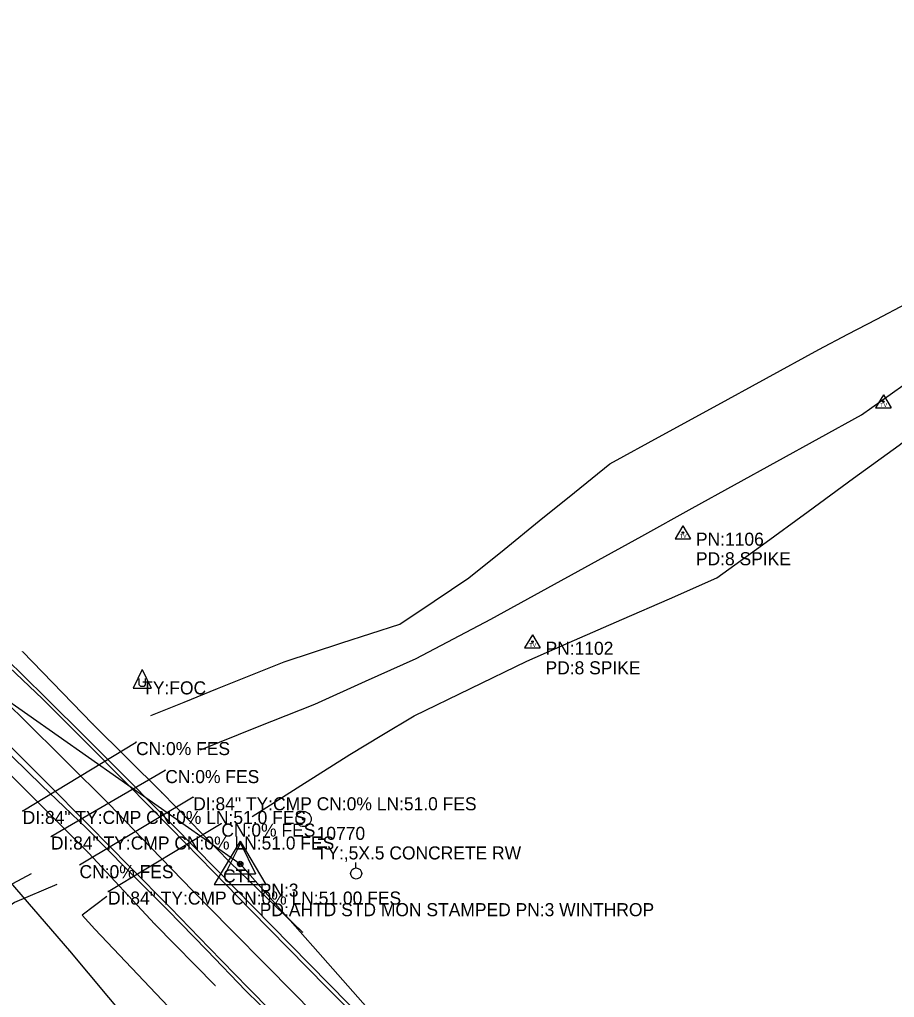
# Model space of a CAD drawing. Extents: x 592653 to 596268, y 1744647 to 1746025.
# Drawn here: x 594132.6 to 594468, y 1745515.6 to 1745890.3 of the extents above; entities that cross this region are included whole.
import ezdxf

# ---------------------------------------------------------------- set-up
doc = ezdxf.new("R2010")
doc.units = 0
for name, color, linetype in [('Default', 7, 'Continuous'), ('S_CAL_CORNER', 7, 'Continuous'), ('S_CROSS_DRAIN', 7, 'Continuous'), ('S_CROSS_DRAIN_ANNOT', 7, 'Continuous'), ('S_DITCHLINE', 7, 'Continuous'), ('S_DRG_PT_SYM', 7, 'Continuous'), ('S_EDGE_PAVEMENT', 7, 'Continuous'), ('S_FENCE', 7, 'Continuous'), ('S_GUARDRAIL', 7, 'Continuous'), ('S_IRON_PIN', 7, 'Continuous'), ('S_IRON_PIN_ANNOT', 7, 'Continuous'), ('S_MSC_PT_SYM', 7, 'Continuous'), ('S_PAVEMENT_CROWN', 7, 'Continuous'), ('S_PRIMARY_CTL', 7, 'Continuous'), ('S_PRIMARY_CTL_ANNOT', 7, 'Continuous'), ('S_RDW_PT_SYM', 7, 'Continuous'), ('S_SECONDARY_CTL', 7, 'Continuous'), ('S_SECONDARY_CTL_ANNOT', 7, 'Continuous'), ('S_SHOULDER', 7, 'Continuous'), ('S_STREAM', 7, 'Continuous'), ('S_UTILITY_POLE', 7, 'Continuous'), ('S_UTILITY_POLE_ANNOT', 7, 'Continuous')]:
    doc.layers.add(name, color=color, linetype=linetype)

msp = doc.modelspace()

# ---------------------------------------------------------------- linework, layer by layer
at = {"layer": 'Default'}
for p, q in [((593756.49, 1745890.31), (594217.16, 1745566.75)), ((594217.16, 1745566.75), (594574.34, 1745162.93))]:
    msp.add_line(p, q, dxfattribs=at)
at = {"layer": 'S_CAL_CORNER'}
for p, q in [((594217.25, 1745574.74), (594211.38, 1745562.92)), ((594217.25, 1745574.74), (594223.06, 1745562.92)), ((594211.38, 1745562.92), (594223.06, 1745562.92))]:
    msp.add_line(p, q, dxfattribs=at)
at = {"layer": 'S_CROSS_DRAIN'}
for p, q in [((594133.77, 1745587.09), (594177.22, 1745613.47)), ((594144.59, 1745577.29), (594188.44, 1745602.74)), ((594199.15, 1745592.32), (594155.56, 1745566.31)), ((594166.49, 1745556.2), (594209.93, 1745582.25))]:
    msp.add_line(p, q, dxfattribs=at)
at = {"layer": 'S_DITCHLINE'}
msp.add_lwpolyline([(594166.09, 1745554.32), (594156.58, 1745547.17), (594161.47, 1745541.73), (594170.83, 1745531.87), (594180.18, 1745522.02), (594189.53, 1745512.16), (594198.89, 1745502.3), (594214.02, 1745482.98), (594229.16, 1745463.65)], dxfattribs=at)
at = {"layer": 'S_DRG_PT_SYM'}
for points in [[(594177.22, 1745613.47), (594177.22, 1745613.52), (594177.22, 1745613.47), (594177.17, 1745613.47), (594177.22, 1745613.47), (594177.22, 1745613.42), (594177.22, 1745613.47), (594177.27, 1745613.47)], [(594188.44, 1745602.74), (594188.44, 1745602.79), (594188.44, 1745602.74), (594188.39, 1745602.74), (594188.44, 1745602.74), (594188.44, 1745602.69), (594188.44, 1745602.74), (594188.49, 1745602.74)], [(594199.15, 1745592.32), (594199.15, 1745592.37), (594199.15, 1745592.32), (594199.1, 1745592.32), (594199.15, 1745592.32), (594199.15, 1745592.27), (594199.15, 1745592.32), (594199.2, 1745592.32)], [(594133.77, 1745587.09), (594133.77, 1745587.14), (594133.77, 1745587.09), (594133.72, 1745587.09), (594133.77, 1745587.09), (594133.77, 1745587.04), (594133.77, 1745587.09), (594133.82, 1745587.09)], [(594209.93, 1745582.25), (594209.93, 1745582.3), (594209.93, 1745582.25), (594209.88, 1745582.25), (594209.93, 1745582.25), (594209.93, 1745582.2), (594209.93, 1745582.25), (594209.98, 1745582.25)], [(594144.59, 1745577.29), (594144.59, 1745577.34), (594144.59, 1745577.29), (594144.54, 1745577.29), (594144.59, 1745577.29), (594144.59, 1745577.24), (594144.59, 1745577.29), (594144.64, 1745577.29)], [(594155.56, 1745566.31), (594155.56, 1745566.36), (594155.56, 1745566.31), (594155.51, 1745566.31), (594155.56, 1745566.31), (594155.56, 1745566.26), (594155.56, 1745566.31), (594155.61, 1745566.31)], [(594166.49, 1745556.2), (594166.49, 1745556.25), (594166.49, 1745556.2), (594166.44, 1745556.2), (594166.49, 1745556.2), (594166.49, 1745556.15), (594166.49, 1745556.2), (594166.54, 1745556.2)]]:
    msp.add_lwpolyline(points, dxfattribs=at)
at = {"layer": 'S_EDGE_PAVEMENT'}
for points in [[(594126.08, 1745644.58), (594141.37, 1745630.02), (594157.62, 1745613.76), (594173.87, 1745597.51), (594190.38, 1745580.64), (594206.89, 1745563.76), (594221.21, 1745549.12), (594235.53, 1745534.47), (594250.34, 1745519.49), (594265.15, 1745504.51)], [(594125.57, 1745615.32), (594142.37, 1745598.49), (594159.17, 1745581.66), (594174.77, 1745565.79), (594190.38, 1745549.93), (594205.32, 1745534.59), (594220.26, 1745519.25), (594229.18, 1745510.28)]]:
    msp.add_lwpolyline(points, dxfattribs=at)
at = {"layer": 'S_FENCE'}
for p, q in [((594104.6, 1745587.97), (594151.71, 1745533.43)), ((594151.71, 1745533.43), (594193.9, 1745483.36))]:
    msp.add_line(p, q, dxfattribs=at)
at = {"layer": 'S_GUARDRAIL'}
for p, q in [((594133.71, 1745648.15), (594160.57, 1745620.5)), ((594160.57, 1745620.5), (594187.09, 1745594.09)), ((594159.03, 1745570.98), (594128.25, 1745601.85)), ((594187.09, 1745594.09), (594213.36, 1745567.33)), ((594184.49, 1745543.72), (594159.03, 1745570.98)), ((594213.36, 1745567.33), (594241.03, 1745540.66)), ((594207.63, 1745520.19), (594184.49, 1745543.72))]:
    msp.add_line(p, q, dxfattribs=at)
at = {"layer": 'S_IRON_PIN'}
for radius in [2.91, 0.411, 0.262, 0.212, 0.145, 0.0822, 0.0581]:
    msp.add_circle((594241.47, 1745583.99), radius, dxfattribs=at)
at = {"layer": 'S_MSC_PT_SYM'}
msp.add_lwpolyline([(594151.71, 1745533.43), (594151.71, 1745533.48), (594151.71, 1745533.43), (594151.66, 1745533.43), (594151.71, 1745533.43), (594151.71, 1745533.38), (594151.71, 1745533.43), (594151.76, 1745533.43)], dxfattribs=at)
at = {"layer": 'S_PAVEMENT_CROWN'}
msp.add_lwpolyline([(594118.8, 1745637.01), (594133.89, 1745622.47), (594150.34, 1745606.11), (594166.78, 1745589.75), (594182.89, 1745573.12), (594198.99, 1745556.49), (594213.38, 1745541.93), (594227.77, 1745527.38), (594236.73, 1745518.28), (594245.68, 1745509.19)], dxfattribs=at)
at = {"layer": 'S_PRIMARY_CTL'}
for p, q in [((594217.16, 1745575.46), (594207.13, 1745558.94)), ((594217.16, 1745575.46), (594207.13, 1745558.94)), ((594217.16, 1745575.46), (594226.99, 1745558.94)), ((594217.16, 1745575.46), (594226.99, 1745558.94)), ((594207.13, 1745558.94), (594226.99, 1745558.94)), ((594207.13, 1745558.94), (594226.99, 1745558.94))]:
    msp.add_line(p, q, dxfattribs=at)
for radius in [1.04, 1.04, 0.609, 0.609, 0.344, 0.344]:
    msp.add_circle((594217.16, 1745566.75), radius, dxfattribs=at)
at = {"layer": 'S_RDW_PT_SYM'}
for points in [[(594133.71, 1745648.15), (594133.71, 1745648.2), (594133.71, 1745648.15), (594133.66, 1745648.15), (594133.71, 1745648.15), (594133.71, 1745648.1), (594133.71, 1745648.15), (594133.76, 1745648.15)], [(594160.57, 1745620.5), (594160.57, 1745620.55), (594160.57, 1745620.5), (594160.52, 1745620.5), (594160.57, 1745620.5), (594160.57, 1745620.45), (594160.57, 1745620.5), (594160.62, 1745620.5)], [(594187.09, 1745594.09), (594187.09, 1745594.14), (594187.09, 1745594.09), (594187.04, 1745594.09), (594187.09, 1745594.09), (594187.09, 1745594.04), (594187.09, 1745594.09), (594187.14, 1745594.09)], [(594159.03, 1745570.98), (594159.03, 1745571.03), (594159.03, 1745570.98), (594158.98, 1745570.98), (594159.03, 1745570.98), (594159.03, 1745570.93), (594159.03, 1745570.98), (594159.08, 1745570.98)], [(594213.36, 1745567.33), (594213.36, 1745567.38), (594213.36, 1745567.33), (594213.31, 1745567.33), (594213.36, 1745567.33), (594213.36, 1745567.28), (594213.36, 1745567.33), (594213.41, 1745567.33)], [(594184.49, 1745543.72), (594184.49, 1745543.77), (594184.49, 1745543.72), (594184.44, 1745543.72), (594184.49, 1745543.72), (594184.49, 1745543.67), (594184.49, 1745543.72), (594184.54, 1745543.72)], [(594241.03, 1745540.66), (594241.03, 1745540.71), (594241.03, 1745540.66), (594240.98, 1745540.66), (594241.03, 1745540.66), (594241.03, 1745540.61), (594241.03, 1745540.66), (594241.08, 1745540.66)], [(594207.63, 1745520.19), (594207.63, 1745520.24), (594207.63, 1745520.19), (594207.58, 1745520.19), (594207.63, 1745520.19), (594207.63, 1745520.14), (594207.63, 1745520.19), (594207.68, 1745520.19)]]:
    msp.add_lwpolyline(points, dxfattribs=at)
at = {"layer": 'S_SECONDARY_CTL'}
for p, q in [((594463.74, 1745746.52), (594460.73, 1745741.57)), ((594463.74, 1745746.52), (594466.68, 1745741.57)), ((594460.73, 1745741.57), (594466.68, 1745741.57)), ((594386.88, 1745696.32), (594383.87, 1745691.36)), ((594386.88, 1745696.32), (594389.83, 1745691.36)), ((594383.87, 1745691.36), (594389.83, 1745691.36)), ((594329.22, 1745654.53), (594326.21, 1745649.57)), ((594329.22, 1745654.53), (594332.16, 1745649.57)), ((594326.21, 1745649.57), (594332.16, 1745649.57))]:
    msp.add_line(p, q, dxfattribs=at)
for centre, radius in [((594463.74, 1745743.91), 0.311), ((594463.74, 1745743.91), 0.183), ((594463.74, 1745743.91), 0.103), ((594386.88, 1745693.71), 0.311), ((594386.88, 1745693.71), 0.183), ((594386.88, 1745693.71), 0.103), ((594329.22, 1745651.92), 0.311), ((594329.22, 1745651.92), 0.183), ((594329.22, 1745651.92), 0.103)]:
    msp.add_circle(centre, radius, dxfattribs=at)
at = {"layer": 'S_SHOULDER'}
for points in [[(594127.14, 1745645.61), (594142.26, 1745630.86), (594158.6, 1745614.55), (594174.94, 1745598.24), (594191.44, 1745581.5), (594207.93, 1745564.76), (594222.2, 1745550.26), (594236.46, 1745535.77), (594251.28, 1745520.68), (594266.09, 1745505.59)], [(594124.11, 1745613.31), (594141.15, 1745596.88), (594158.19, 1745580.45), (594173.73, 1745564.81), (594189.28, 1745549.17), (594204.33, 1745533.69), (594219.37, 1745518.2), (594235.05, 1745502.77)]]:
    msp.add_lwpolyline(points, dxfattribs=at)
at = {"layer": 'S_STREAM'}
for points in [[(594182.93, 1745623.65), (594195.7, 1745628.79), (594208.48, 1745633.93), (594221.25, 1745639.07), (594234.02, 1745644.21), (594256.19, 1745651.45), (594278.36, 1745658.69), (594291.57, 1745667.52), (594304.78, 1745676.35), (594318.3, 1745687.28), (594331.83, 1745698.2), (594345.35, 1745709.13), (594358.88, 1745720.05), (594378.89, 1745731.01), (594398.91, 1745741.98), (594418.92, 1745752.94), (594438.94, 1745763.9), (594450.06, 1745769.71), (594461.18, 1745775.52), (594472.3, 1745781.34), (594483.42, 1745787.15), (594499.58, 1745805.8), (594515.75, 1745824.46)], [(594201.9, 1745610.55), (594223.82, 1745619.26), (594245.73, 1745627.98), (594265.18, 1745636.76), (594284.64, 1745645.55), (594298.92, 1745653.06), (594313.2, 1745660.57), (594332.5, 1745671.18), (594351.81, 1745681.8), (594371.11, 1745692.41), (594390.41, 1745703.03), (594406.66, 1745711.97), (594422.9, 1745720.91), (594439.14, 1745729.85), (594455.39, 1745738.8), (594475.19, 1745752.9), (594494.99, 1745767), (594503.67, 1745778.49), (594512.35, 1745789.98), (594521.03, 1745801.47), (594529.71, 1745812.96)], [(594221.76, 1745584.99), (594240.45, 1745596.85), (594259.15, 1745608.7), (594271.49, 1745616.13), (594283.83, 1745623.55), (594305.45, 1745634.03), (594327.07, 1745644.51), (594345.28, 1745652.47), (594363.49, 1745660.43), (594381.7, 1745668.39), (594399.91, 1745676.35), (594417.38, 1745689.08), (594434.85, 1745701.81), (594452.32, 1745714.54), (594469.8, 1745727.27), (594485.31, 1745739.36), (594500.83, 1745751.44), (594510.33, 1745764.47), (594519.82, 1745777.5), (594529.32, 1745790.53), (594538.82, 1745803.56)], [(594137.06, 1745562.92), (594124.31, 1745556.22), (594111.56, 1745549.51), (594098.82, 1745542.81), (594086.07, 1745536.1), (594071.86, 1745531.58), (594057.65, 1745527.06), (594043.43, 1745522.54), (594029.22, 1745518.02), (594011.13, 1745513.25), (593993.03, 1745508.47), (593980.89, 1745502.69), (593968.75, 1745496.9), (593956.6, 1745491.11), (593944.46, 1745485.33), (593933.64, 1745477.75), (593922.83, 1745470.16), (593907.77, 1745458.25), (593892.71, 1745446.34), (593877.66, 1745434.43), (593862.6, 1745422.52)], [(594146.88, 1745558.89), (594130.58, 1745551.98), (594126.65, 1745549.15), (594111.68, 1745534.37), (594098.81, 1745533.18), (594085.94, 1745531.99), (594072.15, 1745527.89), (594058.36, 1745523.78), (594044.57, 1745519.68), (594030.78, 1745515.57), (594012.34, 1745506.91), (593993.89, 1745498.25), (593982.01, 1745493.42), (593970.13, 1745488.59), (593958.26, 1745483.76), (593946.38, 1745478.93), (593928.65, 1745464.69), (593914.46, 1745451.61), (593900.27, 1745438.53), (593886.09, 1745425.45), (593871.9, 1745412.37)]]:
    msp.add_lwpolyline(points, dxfattribs=at)
at = {"layer": 'S_UTILITY_POLE'}
for p, q in [((594179.59, 1745641.27), (594176.07, 1745634.18)), ((594179.59, 1745641.27), (594183.08, 1745634.18)), ((594178.39, 1745635.42), (594178.39, 1745637.86)), ((594179.01, 1745634.76), (594178.39, 1745635.42)), ((594180.21, 1745634.76), (594179.01, 1745634.76)), ((594180.76, 1745635.42), (594180.21, 1745634.76)), ((594180.76, 1745637.86), (594180.76, 1745635.42)), ((594176.07, 1745634.18), (594183.08, 1745634.18)), ((594261.49, 1745565.26), (594261.49, 1745567.36))]:
    msp.add_line(p, q, dxfattribs=at)
msp.add_circle((594261.61, 1745563.11), 2.13, dxfattribs=at)

# ---------------------------------------------------------------- texts
at = {"layer": 'S_CROSS_DRAIN_ANNOT'}
for s, p in [('CN:0% FES', (594177.22, 1745608.47)), ('CN:0% FES', (594188.44, 1745597.74)), ('DI:84" TY:CMP CN:0% LN:51.0 FES', (594199.15, 1745587.32)), ('DI:84" TY:CMP CN:0% LN:51.0 FES', (594133.77, 1745582.09)), ('CN:0% FES', (594209.93, 1745577.25)), ('DI:84" TY:CMP CN:0% LN:51.0 FES', (594144.59, 1745572.29)), ('CN:0% FES', (594155.56, 1745561.31)), ('DI:84" TY:CMP CN:0% LN:51.00 FES', (594166.49, 1745551.2))]:
    msp.add_text(s, height=5, dxfattribs=at).set_placement(p)
at = {"layer": 'S_IRON_PIN_ANNOT'}
for s, p in [('10770', (594246.47, 1745575.99)), ('TY:,5X.5 CONCRETE RW', (594246.47, 1745568.49))]:
    msp.add_text(s, height=5, dxfattribs=at).set_placement(p)
at = {"layer": 'S_PRIMARY_CTL'}
msp.add_text('CTL', height=5, rotation=360, dxfattribs=at).set_placement((594210.58, 1745559.68))
msp.add_text('CTL', height=5, rotation=360, dxfattribs=at).set_placement((594210.58, 1745559.68))
at = {"layer": 'S_PRIMARY_CTL_ANNOT'}
for s, p in [('PN:3', (594224.66, 1745554.25)), ('PD:AHTD STD MON STAMPED PN:3 WINTHROP', (594224.66, 1745546.75))]:
    msp.add_text(s, height=5, dxfattribs=at).set_placement(p)
at = {"layer": 'S_SECONDARY_CTL'}
for p in [(594462.53, 1745741.9), (594385.68, 1745691.7), (594328.01, 1745649.9)]:
    msp.add_text('TV', height=1.5, rotation=360, dxfattribs=at).set_placement(p)
at = {"layer": 'S_SECONDARY_CTL_ANNOT'}
for s, p in [('PN:1106', (594391.88, 1745688.71)), ('PD:8 SPIKE', (594391.88, 1745681.21)), ('PN:1102', (594334.22, 1745646.92)), ('PD:8 SPIKE', (594334.22, 1745639.42))]:
    msp.add_text(s, height=5, dxfattribs=at).set_placement(p)
at = {"layer": 'S_UTILITY_POLE_ANNOT'}
msp.add_text('TY:FOC', height=5, dxfattribs=at).set_placement((594179.59, 1745631.74))

doc.saveas('drawing.dxf')
